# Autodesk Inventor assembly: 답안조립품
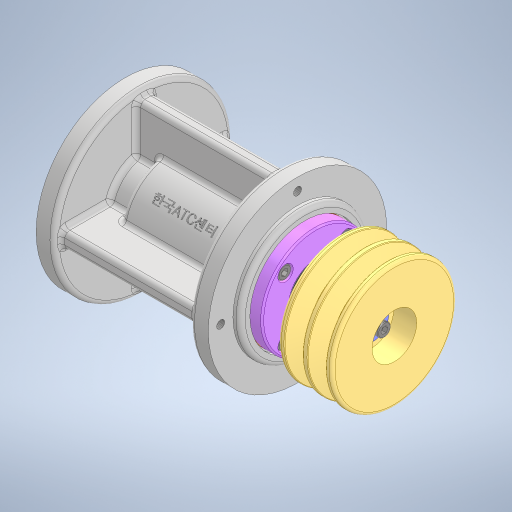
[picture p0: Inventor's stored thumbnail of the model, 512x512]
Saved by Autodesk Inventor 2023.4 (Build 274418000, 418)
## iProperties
Created: 2024-10
Part Number: 답안조립품
Document SubType Name: Assembly
Designer: 11
Author: 11
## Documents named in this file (18)
- C:\Users\11\Desktop\741004V1009\답안조립품.iam
- C:\Users\11\Desktop\741004V1009\본체.ipt
- C:\Users\11\Desktop\741004V1009\V 벨트 풀리\V 벨트 풀리.ipt
- C:\Users\11\Desktop\741004V1009\가스켓\가스켓.ipt
- C:\Users\11\Desktop\741004V1009\깊은 홈 볼베어링 6004\깊은 홈 볼베어링 6004.ipt
- C:\Users\11\Desktop\741004V1009\스러스트 볼베어링 512 02\스러스트 볼베어링 512 02.ipt
- C:\Users\11\Desktop\741004V1009\스프링와셔 M5\스프링와셔 M5.ipt
- C:\Users\11\Desktop\741004V1009\실링 패드\실링 패드.ipt
- C:\Users\11\Desktop\741004V1009\어뎁터\어뎁터.ipt
- C:\Users\11\Desktop\741004V1009\엔드캡\엔드캡.ipt
- C:\Users\11\Desktop\741004V1009\오일 실 20 35 8\오일 실 20 35 8.ipt
- C:\Users\11\Desktop\741004V1009\육각 머리 볼트 M6x0.75x12\육각 머리 볼트 M6x0.75x12.ipt
- C:\Users\11\Desktop\741004V1009\육각 소켓 머리 볼트 M5x10\육각 소켓 머리 볼트 M5x10.ipt
- C:\Users\11\Desktop\741004V1009\축\축.ipt
- C:\Users\11\Desktop\741004V1009\칼라\칼라.ipt
- C:\Users\11\Desktop\741004V1009\커버\커버.ipt
- C:\Users\11\Desktop\741004V1009\평와셔 M5\평와셔 M5.ipt
- C:\Users\11\Desktop\741004V1009\평행키 5x5x22\평행키 5x5x22.ipt
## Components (2 placed, 2 different names)
1. V 벨트 풀리:1
2. 가스켓:1
